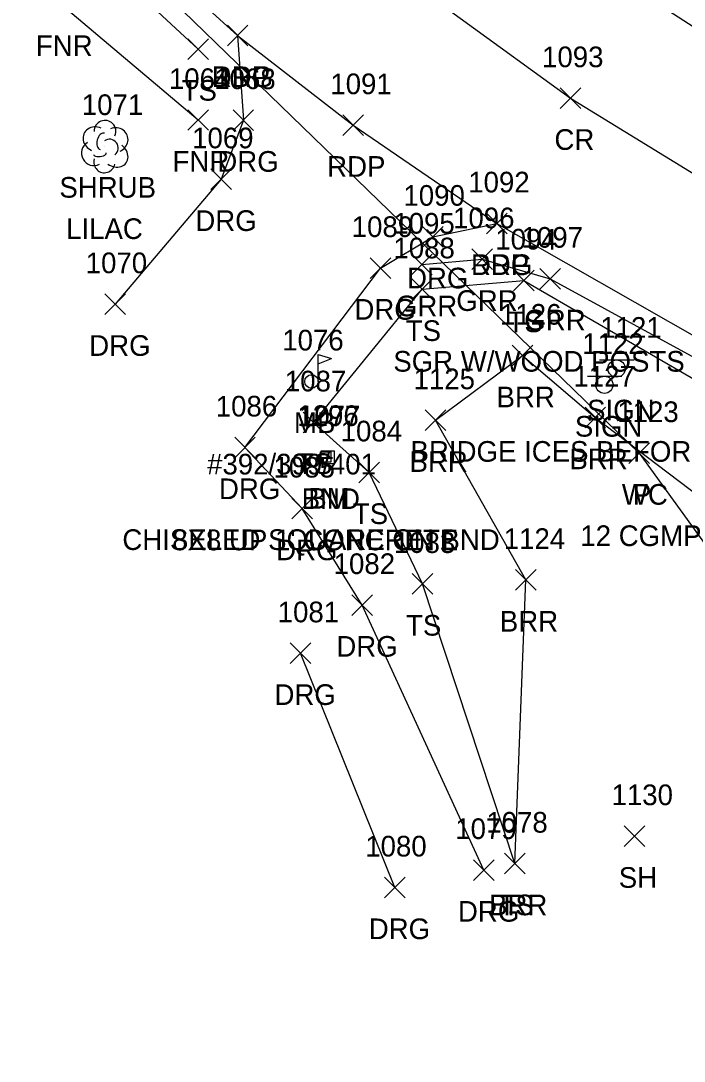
# Model space of a CAD drawing. Extents: x 1761340 to 1763889, y 696770 to 706023.
# Drawn here: x 1761454.8 to 1761519.1, y 700813.2 to 700913.9 of the extents above; entities that cross this region are included whole.
import ezdxf

# ---------------------------------------------------------------- set-up
doc = ezdxf.new("R2010")
doc.units = 0
for name, color, linetype in [('C_A', 7, 'Continuous'), ('C_C', 7, 'Continuous'), ('C_I', 7, 'Continuous'), ('CPBM', 7, 'Continuous'), ('D_A', 7, 'Continuous'), ('D_C', 7, 'Continuous'), ('D_I', 7, 'Continuous'), ('D_TIC', 7, 'Continuous'), ('DCP', 7, 'Continuous'), ('L_A', 7, 'Continuous'), ('L_C', 7, 'Continuous'), ('L_I', 7, 'Continuous'), ('L_TIC', 7, 'Continuous'), ('LABL', 7, 'Continuous'), ('LAWE', 7, 'Continuous'), ('LELB', 7, 'Continuous'), ('LFNC', 7, 'Continuous'), ('LMB', 7, 'Continuous'), ('LSH', 7, 'Continuous'), ('M_A', 7, 'Continuous'), ('M_C', 7, 'Continuous'), ('M_I', 7, 'Continuous'), ('MHBP', 7, 'Continuous'), ('P_A', 7, 'Continuous'), ('P_I', 7, 'Continuous'), ('P_TIC', 7, 'Continuous'), ('PET', 7, 'Continuous'), ('PRC', 7, 'Continuous'), ('R_A', 7, 'Continuous'), ('R_C', 7, 'Continuous'), ('R_I', 7, 'Continuous'), ('R_TIC', 7, 'Continuous'), ('RDG', 7, 'Continuous'), ('RGR', 7, 'Continuous'), ('S_A', 7, 'Continuous'), ('S_C', 7, 'Continuous'), ('S_I', 7, 'Continuous'), ('SSGN', 7, 'Continuous')]:
    doc.layers.add(name, color=color, linetype=linetype)

msp = doc.modelspace()

# ---------------------------------------------------------------- linework, layer by layer
at = {"layer": 'CPBM'}
for p, q in [((1761483.82, 700871.19), (1761483.82, 700872.19)), ((1761483.82, 700872.19), (1761484.82, 700872.19)), ((1761484.33, 700871.69), (1761484.33, 700871.69)), ((1761484.33, 700871.69), (1761484.33, 700871.69)), ((1761484.82, 700872.19), (1761484.82, 700871.19)), ((1761484.82, 700871.19), (1761483.82, 700871.19))]:
    msp.add_line(p, q, dxfattribs=at)
at = {"layer": 'D_TIC'}
for points in [[(1761513.71, 700871.07), (1761515.71, 700873.07)], [(1761515.71, 700871.07), (1761513.71, 700873.07)]]:
    msp.add_lwpolyline(points, dxfattribs=at)
at = {"layer": 'DCP'}
msp.add_lwpolyline([(1761416.81, 700966.84), (1761514.71, 700872.07)], dxfattribs=at)
at = {"layer": 'L_TIC'}
for points in [[(1761470.96, 700910.18), (1761472.96, 700912.18)], [(1761472.96, 700910.18), (1761470.96, 700912.18)], [(1761470.96, 700903.31), (1761472.96, 700905.31)], [(1761472.96, 700903.31), (1761470.96, 700905.31)], [(1761492.67, 700886.92), (1761494.67, 700888.92)], [(1761494.67, 700886.92), (1761492.67, 700888.92)], [(1761502.53, 700887.77), (1761504.53, 700889.77)], [(1761504.53, 700887.77), (1761502.53, 700889.77)], [(1761502.4, 700880.5), (1761504.4, 700882.5)], [(1761504.4, 700880.5), (1761502.4, 700882.5)], [(1761482.14, 700874.04), (1761484.14, 700876.04)], [(1761484.14, 700874.04), (1761482.14, 700876.04)], [(1761493.96, 700874.25), (1761495.96, 700876.25)], [(1761495.96, 700874.25), (1761493.96, 700876.25)], [(1761509.45, 700874.51), (1761511.45, 700876.51)], [(1761511.45, 700874.51), (1761509.45, 700876.51)], [(1761513.71, 700871.07), (1761515.71, 700873.07)], [(1761515.71, 700871.07), (1761513.71, 700873.07)], [(1761487.55, 700869.2), (1761489.55, 700871.2)], [(1761489.55, 700869.2), (1761487.55, 700871.2)], [(1761502.71, 700858.79), (1761504.71, 700860.79)], [(1761504.71, 700858.79), (1761502.71, 700860.79)], [(1761492.7, 700858.4), (1761494.7, 700860.4)], [(1761494.7, 700858.4), (1761492.7, 700860.4)], [(1761513.24, 700833.99), (1761515.24, 700835.99)], [(1761515.24, 700833.99), (1761513.24, 700835.99)], [(1761501.66, 700831.33), (1761503.66, 700833.33)], [(1761503.66, 700831.33), (1761501.66, 700833.33)], [(1761501.66, 700831.33), (1761503.66, 700833.33)], [(1761503.66, 700831.33), (1761501.66, 700833.33)]]:
    msp.add_lwpolyline(points, dxfattribs=at)
at = {"layer": 'LABL'}
msp.add_lwpolyline([(1761502.66, 700832.33), (1761503.71, 700859.79), (1761494.96, 700875.25), (1761503.4, 700881.5), (1761510.45, 700875.51), (1761532.73, 700858.63), (1761547.41, 700844.77), (1761568.49, 700834.64), (1761575.59, 700833.99)], dxfattribs=at)
at = {"layer": 'LAWE'}
msp.add_lwpolyline([(1761514.71, 700872.07), (1761528.13, 700853.52), (1761542.13, 700836.59), (1761554.23, 700813.21), (1761575.51, 700815.64)], dxfattribs=at)
at = {"layer": 'LELB'}
for points in [[(1761420.87, 700964.35), (1761431.27, 700953.03), (1761451.42, 700930.17), (1761471.96, 700911.18)], [(1761502.66, 700832.33), (1761493.7, 700859.4), (1761488.55, 700870.2), (1761483.14, 700875.04), (1761493.67, 700887.92), (1761503.53, 700888.77), (1761525.81, 700875.88), (1761549.64, 700863.05), (1761575.92, 700850.18), (1761596.96, 700845.7)]]:
    msp.add_lwpolyline(points, dxfattribs=at)
at = {"layer": 'LFNC'}
msp.add_lwpolyline([(1761425.44, 700949.08), (1761447.68, 700926.67), (1761458.72, 700915.5), (1761471.96, 700904.31)], dxfattribs=at)
at = {"layer": 'LMB'}
for p, q in [((1761483.6, 700881.6), (1761484.89, 700881.22)), ((1761483.6, 700879.01), (1761483.6, 700881.6)), ((1761483.6, 700880.7), (1761484.88, 700881.21)), ((1761482.95, 700879), (1761482.95, 700879))]:
    msp.add_line(p, q, dxfattribs=at)
msp.add_circle((1761482.95, 700879), 0.656, dxfattribs=at)
at = {"layer": 'LSH'}
msp.add_line((1761462.9, 700901.79), (1761462.9, 700901.79), dxfattribs=at)
msp.add_line((1761462.9, 700901.79), (1761462.9, 700901.79), dxfattribs=at)
msp.add_arc((1761462.95, 700903.22), 1.05, 335.5272, 180.9563, dxfattribs=at)
for centre, major_axis, ratio, start_param, end_param in [((1761462.11, 700902.45), (1.21, -0.51), 0.895232, 1.570796, 4.712389), ((1761462.7, 700902.24), (-0.208, -0.792), 0.645439, 3.141593, 6.283185), ((1761463.95, 700902.37), (-1.14, -0.48), 0.949671, 1.570796, 4.712389), ((1761461.82, 700901.08), (0.58, -1.04), 0.959034, 3.141593, 6.283185), ((1761463.4, 700901.62), (-0.5, 0.667), 0.989748, 3.141593, 6.283185), ((1761463.9, 700900.95), (-1.09, 0.79), 0.841452, 1.570796, 4.712389), ((1761462.45, 700901.04), (-0.625, -0.083), 0.423636, 0, 3.141593), ((1761462.9, 700900.29), (0.26, 1.06), 0.942809, 1.570796, 4.712389)]:
    msp.add_ellipse(centre, major_axis=major_axis, ratio=ratio, start_param=start_param, end_param=end_param, dxfattribs=at)
at = {"layer": 'MHBP'}
msp.add_lwpolyline([(1761483.89, 700872.28), (1761485.14, 700872.28), (1761485.14, 700871.03), (1761483.89, 700871.03)], close=True, dxfattribs=at)
msp.add_circle((1761484.51, 700871.66), 0.0833, dxfattribs=at)
at = {"layer": 'P_TIC'}
for points in [[(1761474.8, 700911.49), (1761476.8, 700913.49)], [(1761476.8, 700911.49), (1761474.8, 700913.49)], [(1761507.06, 700905.42), (1761509.06, 700907.42)], [(1761509.06, 700905.42), (1761507.06, 700907.42)], [(1761485.98, 700902.81), (1761487.98, 700904.81)], [(1761487.98, 700902.81), (1761485.98, 700904.81)], [(1761499.92, 700893.3), (1761501.92, 700895.3)], [(1761501.92, 700893.3), (1761499.92, 700895.3)]]:
    msp.add_lwpolyline(points, dxfattribs=at)
at = {"layer": 'PET'}
for points in [[(1761565.69, 700887.32), (1761551.93, 700894.01), (1761537.2, 700902.21), (1761507.2, 700921.56), (1761485.83, 700936.45), (1761463.82, 700956.86), (1761451.66, 700968.66), (1761442.59, 700979.07), (1761431.29, 700993.83), (1761424.05, 701005.24), (1761416.58, 701016.18), (1761400.04, 701039.88), (1761381.47, 701065.28)], [(1761361.55, 701051.07), (1761381.35, 701023.89), (1761395.32, 701004.39), (1761414.57, 700977.92), (1761433.71, 700954.24), (1761453.66, 700932.57), (1761475.8, 700912.49), (1761486.98, 700903.81), (1761500.92, 700894.3), (1761527.65, 700879.06), (1761551.01, 700866.82), (1761575.84, 700857.11)]]:
    msp.add_lwpolyline(points, dxfattribs=at)
at = {"layer": 'PRC'}
msp.add_lwpolyline([(1761371.66, 701058.14), (1761390.63, 701031.26), (1761404.65, 701011.45), (1761424.14, 700986), (1761443.93, 700962.2), (1761463.21, 700942.49), (1761486.68, 700921.95), (1761508.06, 700906.42), (1761533.51, 700890.82), (1761557.04, 700878.89), (1761580.26, 700869.03), (1761600.69, 700862.06)], dxfattribs=at)
at = {"layer": 'R_TIC'}
for points in [[(1761474.8, 700911.49), (1761476.8, 700913.49)], [(1761476.8, 700911.49), (1761474.8, 700913.49)], [(1761475.35, 700903.3), (1761477.35, 700905.3)], [(1761477.35, 700903.3), (1761475.35, 700905.3)], [(1761473.21, 700897.57), (1761475.21, 700899.57)], [(1761475.21, 700897.57), (1761473.21, 700899.57)], [(1761499.92, 700893.3), (1761501.92, 700895.3)], [(1761501.92, 700893.3), (1761499.92, 700895.3)], [(1761493.72, 700892.01), (1761495.72, 700894.01)], [(1761495.72, 700892.01), (1761493.72, 700894.01)], [(1761498.5, 700889.83), (1761500.5, 700891.83)], [(1761500.5, 700889.83), (1761498.5, 700891.83)], [(1761488.63, 700888.98), (1761490.63, 700890.98)], [(1761490.63, 700888.98), (1761488.63, 700890.98)], [(1761492.65, 700889.31), (1761494.65, 700891.31)], [(1761494.65, 700889.31), (1761492.65, 700891.31)], [(1761505.08, 700887.95), (1761507.08, 700889.95)], [(1761507.08, 700887.95), (1761505.08, 700889.95)], [(1761462.94, 700885.48), (1761464.94, 700887.48)], [(1761464.94, 700885.48), (1761462.94, 700887.48)], [(1761475.51, 700871.61), (1761477.51, 700873.61)], [(1761477.51, 700871.61), (1761475.51, 700873.61)], [(1761481.04, 700865.7), (1761483.04, 700867.7)], [(1761483.04, 700865.7), (1761481.04, 700867.7)], [(1761486.87, 700856.36), (1761488.87, 700858.36)], [(1761488.87, 700856.36), (1761486.87, 700858.36)], [(1761480.89, 700851.69), (1761482.89, 700853.69)], [(1761482.89, 700851.69), (1761480.89, 700853.69)], [(1761498.65, 700830.71), (1761500.65, 700832.71)], [(1761500.65, 700830.71), (1761498.65, 700832.71)], [(1761490.02, 700829.02), (1761492.02, 700831.02)], [(1761492.02, 700829.02), (1761490.02, 700831.02)]]:
    msp.add_lwpolyline(points, dxfattribs=at)
at = {"layer": 'RDG'}
for points in [[(1761475.8, 700912.49), (1761476.35, 700904.3), (1761474.21, 700898.57), (1761463.94, 700886.48)], [(1761499.65, 700831.71), (1761487.87, 700857.36), (1761482.04, 700866.7), (1761476.51, 700872.61), (1761489.63, 700889.98), (1761494.72, 700893.01), (1761500.92, 700894.3)], [(1761491.02, 700830.02), (1761481.89, 700852.69)]]:
    msp.add_lwpolyline(points, dxfattribs=at)
at = {"layer": 'RGR'}
msp.add_lwpolyline([(1761493.65, 700890.31), (1761499.5, 700890.83), (1761506.08, 700888.95), (1761526.77, 700877.63), (1761550.69, 700865.76), (1761575.7, 700856.34), (1761588.64, 700851.95), (1761598.08, 700849.06)], dxfattribs=at)
at = {"layer": 'SSGN'}
for p, q in [((1761510.87, 700881.08), (1761514.2, 700881.08)), ((1761512.51, 700880.25), (1761512.51, 700880.25)), ((1761509.68, 700879.52), (1761513.02, 700879.52)), ((1761511.33, 700878.68), (1761511.33, 700878.68))]:
    msp.add_line(p, q, dxfattribs=at)
for centre in [(1761512.51, 700880.25), (1761511.33, 700878.68)]:
    msp.add_circle(centre, 0.833, dxfattribs=at)

# ---------------------------------------------------------------- texts
at = {"layer": 'C_A'}
msp.add_text('BM', height=2, dxfattribs=at).set_placement((1761482.64, 700866.69))
at = {"layer": 'C_C'}
msp.add_text('CHISELED SQUARE ON BND', height=2, dxfattribs=at).set_placement((1761464.63, 700862.69))
at = {"layer": 'C_I'}
msp.add_text('1296', height=2, dxfattribs=at).set_placement((1761481.58, 700874.69))
at = {"layer": 'D_A'}
msp.add_text('P', height=2, dxfattribs=at).set_placement((1761514.09, 700867.07))
at = {"layer": 'D_C'}
msp.add_text('12 CGMP', height=2, dxfattribs=at).set_placement((1761509, 700863.07))
at = {"layer": 'D_I'}
msp.add_text('1123', height=2, dxfattribs=at).set_placement((1761512.58, 700875.07))
at = {"layer": 'L_A'}
for s, p in [('FNR', (1761456.25, 700910.5)), ('TS', (1761470.37, 700906.18)), ('FNR', (1761469.49, 700899.31)), ('SHRUB', (1761458.53, 700896.79)), ('TS', (1761501.94, 700883.77)), ('TS', (1761492.08, 700882.92)), ('BRR', (1761500.88, 700876.5)), ('MB', (1761481.25, 700874)), ('TS', (1761481.55, 700870.04)), ('BRR', (1761492.45, 700870.25)), ('BRR', (1761507.94, 700870.51)), ('WC', (1761513.02, 700867.07)), ('TS', (1761486.96, 700865.2)), ('BRR', (1761501.2, 700854.79)), ('TS', (1761492.11, 700854.4)), ('SH', (1761512.72, 700829.99)), ('TS', (1761501.07, 700827.33)), ('BRR', (1761500.15, 700827.33))]:
    msp.add_text(s, height=2, dxfattribs=at).set_placement(p)
at = {"layer": 'L_C'}
for s, p in [('LILAC', (1761459.18, 700892.79)), ('#392/399/401', (1761472.84, 700870))]:
    msp.add_text(s, height=2, dxfattribs=at).set_placement(p)
at = {"layer": 'L_I'}
for s, p in [('1064', (1761469.14, 700907.31)), ('1071', (1761460.7, 700904.79)), ('1088', (1761490.89, 700890.92)), ('1094', (1761500.76, 700891.77)), ('1126', (1761501.22, 700884.5)), ('1076', (1761480.12, 700882)), ('1087', (1761480.37, 700878.04)), ('1125', (1761492.84, 700878.25)), ('1127', (1761508.33, 700878.51)), ('1123', (1761512.58, 700875.07)), ('1084', (1761485.78, 700873.2)), ('1124', (1761501.58, 700862.79)), ('1083', (1761490.93, 700862.4)), ('1130', (1761512.02, 700837.99)), ('1078', (1761499.89, 700835.33)), ('1078', (1761499.89, 700835.33))]:
    msp.add_text(s, height=2, dxfattribs=at).set_placement(p)
at = {"layer": 'M_A'}
msp.add_text('BND', height=2, dxfattribs=at).set_placement((1761482, 700866.66))
at = {"layer": 'M_C'}
msp.add_text("8X8 UP 1' CONCRETE", height=2, dxfattribs=at).set_placement((1761469.46, 700862.66))
at = {"layer": 'M_I'}
msp.add_text('1077', height=2, dxfattribs=at).set_placement((1761481.74, 700874.66))
at = {"layer": 'P_A'}
for s, p in [('RDP', (1761473.29, 700907.49)), ('CR', (1761506.49, 700901.42)), ('RDP', (1761484.47, 700898.81)), ('RDP', (1761498.4, 700889.3))]:
    msp.add_text(s, height=2, dxfattribs=at).set_placement(p)
at = {"layer": 'P_I'}
for s, p in [('1093', (1761505.29, 700909.42)), ('1091', (1761484.78, 700906.81)), ('1092', (1761498.14, 700897.3))]:
    msp.add_text(s, height=2, dxfattribs=at).set_placement(p)
at = {"layer": 'R_A'}
for s, p in [('DRG', (1761473.29, 700907.49)), ('DRG', (1761473.83, 700899.3)), ('DRG', (1761471.7, 700893.57)), ('DRG', (1761498.4, 700889.3)), ('DRG', (1761492.21, 700888.01)), ('GRR', (1761496.98, 700885.83)), ('DRG', (1761487.11, 700884.98)), ('GRR', (1761491.13, 700885.31)), ('GRR', (1761503.57, 700883.95)), ('DRG', (1761461.42, 700881.48)), ('DRG', (1761473.99, 700867.61)), ('DRG', (1761479.53, 700861.7)), ('DRG', (1761485.36, 700852.36)), ('DRG', (1761479.37, 700847.69)), ('DRG', (1761497.14, 700826.71)), ('DRG', (1761488.5, 700825.02))]:
    msp.add_text(s, height=2, dxfattribs=at).set_placement(p)
at = {"layer": 'R_C'}
msp.add_text('SGR W/WOOD POSTS', height=2, dxfattribs=at).set_placement((1761490.88, 700879.95))
at = {"layer": 'R_I'}
for s, p in [('1068', (1761473.53, 700907.3)), ('1069', (1761471.39, 700901.57)), ('1092', (1761498.14, 700897.3)), ('1090', (1761491.86, 700896.01)), ('1096', (1761496.67, 700893.83)), ('1089', (1761486.85, 700892.98)), ('1095', (1761490.88, 700893.31)), ('1097', (1761503.31, 700891.95)), ('1070', (1761461.08, 700889.48)), ('1086', (1761473.68, 700875.61)), ('1085', (1761479.27, 700869.7)), ('1082', (1761485.1, 700860.36)), ('1081', (1761479.68, 700855.69)), ('1079', (1761496.88, 700834.71)), ('1080', (1761488.16, 700833.02))]:
    msp.add_text(s, height=2, dxfattribs=at).set_placement(p)
at = {"layer": 'S_A'}
for p in [(1761509.65, 700875.23), (1761508.47, 700873.66)]:
    msp.add_text('SIGN', height=2, dxfattribs=at).set_placement(p)
at = {"layer": 'S_C'}
msp.add_text('BRIDGE ICES BEFORE ROAD', height=2, dxfattribs=at).set_placement((1761492.55, 700871.23))
at = {"layer": 'S_I'}
for s, p in [('1121', (1761510.93, 700883.23)), ('1122', (1761509.18, 700881.66))]:
    msp.add_text(s, height=2, dxfattribs=at).set_placement(p)

doc.saveas('drawing.dxf')
